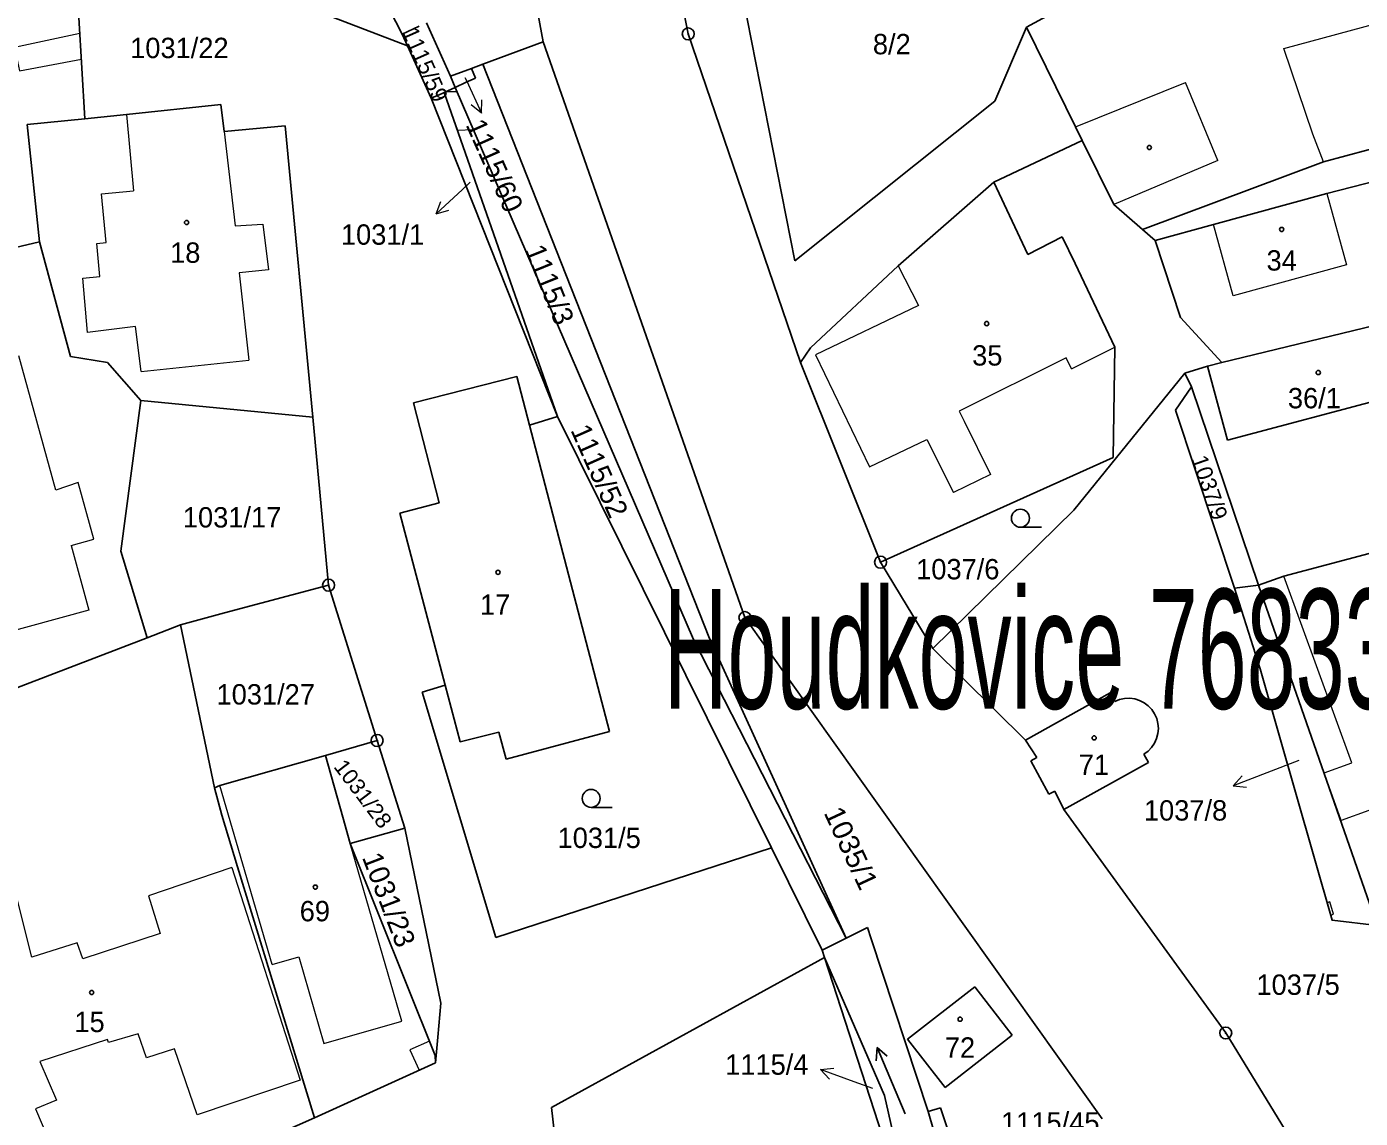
# Model space of a CAD drawing. Extents: x -618848 to -615803, y -1044450 to -1042254.
# Drawn here: x -617086 to -616974.7, y -1043060.3 to -1042969.1 of the extents above; entities that cross this region are included whole.
import ezdxf
from ezdxf.enums import TextEntityAlignment as Align

# ---------------------------------------------------------------- set-up
doc = ezdxf.new("R2010")
doc.units = 0
doc.header["$LTSCALE"] = 0.68
for name, color, linetype, lineweight in [('1', 7, 'Continuous', 25), ('13', 7, 'Continuous', 13), ('3', 7, 'Continuous', 25), ('4', 7, 'Continuous', 13), ('5', 7, 'Continuous', 25), ('7', 7, 'Continuous', 13), ('8', 7, 'Continuous', 25)]:
    doc.layers.add(name, color=color, linetype=linetype, lineweight=lineweight)
doc.layers.add('2', color=7, linetype='Continuous')

msp = doc.modelspace()

# ---------------------------------------------------------------- linework, layer by layer
at = {"layer": '1'}
for p, q in [((-617043.53, -1042906.35), (-617030.78, -1042969.76)), ((-617047.51, -1042945.2), (-617042.89, -1042970.41)), ((-617058.05, -1042963.13), (-617054.66, -1042969.77)), ((-617026.28, -1042966.26), (-617021.89, -1042988.71)), ((-617064.32, -1042966.86), (-617054.22, -1042970.74)), ((-617002.54, -1042969.19), (-616998.53, -1042967.03)), ((-617081.64, -1042968.39), (-617081.14, -1042976.85)), ((-617053.24, -1042969.11), (-617054.66, -1042969.77)), ((-617052.62, -1042968.82), (-617050.63, -1042973.29)), ((-617002.54, -1042969.19), (-617005.19, -1042975.38)), ((-617002.54, -1042969.19), (-616998.44, -1042977.52)), ((-617054.22, -1042970.74), (-617054.66, -1042969.77)), ((-617052.23, -1042975.13), (-617054.22, -1042970.74)), ((-617047.92, -1042972.28), (-617042.89, -1042970.41)), ((-617042.89, -1042970.41), (-617026.04, -1043018.49)), ((-617021.4, -1042997.18), (-617030.78, -1042969.76)), ((-616977.74, -1042980.44), (-616945.54, -1042971.66)), ((-617050.63, -1042973.29), (-617048.88, -1042972.64)), ((-617048.88, -1042972.64), (-617047.92, -1042972.28)), ((-617048.88, -1042972.64), (-617048.54, -1042973.44)), ((-617047.92, -1042972.28), (-617029.07, -1043020.1)), ((-617050.63, -1042973.29), (-617050.23, -1042974.22)), ((-617048.54, -1042973.44), (-617049.31, -1042973.79)), ((-617052.23, -1042975.13), (-617051.31, -1042974.72)), ((-617052.23, -1042975.13), (-617041.69, -1043001.71)), ((-617051.31, -1042974.72), (-617051.15, -1042974.65)), ((-617051.15, -1042974.65), (-617041.69, -1043001.71)), ((-617050.23, -1042974.22), (-617030.33, -1043020.31)), ((-617077.67, -1042976.48), (-617069.79, -1042975.66)), ((-617069.79, -1042975.66), (-617069.53, -1042977.91)), ((-617005.19, -1042975.38), (-617021.89, -1042988.71)), ((-617085.97, -1042977.32), (-617081.14, -1042976.85)), ((-617085.97, -1042977.32), (-617084.93, -1042987.12)), ((-617081.14, -1042976.85), (-617077.67, -1042976.48)), ((-617069.53, -1042977.91), (-617064.42, -1042977.43)), ((-617062.13, -1043001.76), (-617064.42, -1042977.43)), ((-616998.44, -1042977.52), (-616997.89, -1042978.64)), ((-617005.26, -1042982.12), (-616997.89, -1042978.64)), ((-616997.89, -1042978.64), (-616995.25, -1042984.01)), ((-616992.84, -1042986.09), (-616977.74, -1042980.44)), ((-616977.45, -1042983.07), (-616966.6, -1042980.27)), ((-617005.26, -1042982.12), (-617013.24, -1042989.13)), ((-617002.42, -1042988.18), (-617005.26, -1042982.12)), ((-616986.92, -1042985.66), (-616977.45, -1042983.07)), ((-616995.25, -1042984.01), (-616992.84, -1042986.09)), ((-616992.84, -1042986.09), (-616991.78, -1042987.01)), ((-616991.78, -1042987.01), (-616986.92, -1042985.66)), ((-617084.93, -1042987.12), (-617098.16, -1042990.2)), ((-617084.93, -1042987.12), (-617082.34, -1042996.69)), ((-616999.56, -1042986.7), (-617002.42, -1042988.18)), ((-616998.48, -1042988.92), (-616999.56, -1042986.7)), ((-616991.78, -1042987.01), (-616989.68, -1042993.44)), ((-617013.24, -1042989.13), (-617020.57, -1042995.97)), ((-616995.15, -1042995.92), (-616998.48, -1042988.92)), ((-616989.68, -1042993.44), (-616986.24, -1042997.18)), ((-617020.57, -1042995.97), (-617021.4, -1042997.18)), ((-616995.29, -1043005.13), (-616995.15, -1042995.92)), ((-617082.34, -1042996.69), (-617079.25, -1042997.2)), ((-617079.25, -1042997.2), (-617076.49, -1043000.36)), ((-617014.72, -1043013.86), (-617021.4, -1042997.18)), ((-616989.33, -1042998.09), (-616987.42, -1042997.5)), ((-616986.24, -1042997.18), (-616987.42, -1042997.5)), ((-616987.42, -1042997.5), (-616985.76, -1043003.68)), ((-617053.71, -1043000.57), (-617045.09, -1042998.36)), ((-617045.09, -1042998.36), (-617044.03, -1043002.41)), ((-616998.58, -1043009.51), (-616989.33, -1042998.09)), ((-616989.33, -1042998.09), (-616988.76, -1042999.23)), ((-616985.76, -1043003.68), (-616966.15, -1042998.47)), ((-616990.1, -1043001.17), (-616988.76, -1042999.23)), ((-616988.76, -1042999.23), (-616983.16, -1043015.79)), ((-617076.49, -1043000.36), (-617078.16, -1043012.93)), ((-617062.13, -1043001.76), (-617076.49, -1043000.36)), ((-617051.57, -1043008.91), (-617053.71, -1043000.57)), ((-617062.13, -1043001.76), (-617061.54, -1043008.01)), ((-617044.03, -1043002.41), (-617041.69, -1043001.71)), ((-617041.69, -1043001.71), (-617023.83, -1043037.72)), ((-616985.17, -1043016.04), (-616990.1, -1043001.17)), ((-617044.03, -1043002.41), (-617037.34, -1043028)), ((-617014.72, -1043013.86), (-616995.29, -1043005.13)), ((-617061.54, -1043008.01), (-617061.2, -1043011.6)), ((-617054.85, -1043009.77), (-617051.57, -1043008.91)), ((-617051.07, -1043024.13), (-617054.85, -1043009.77)), ((-617010.36, -1043021.08), (-616998.58, -1043009.51)), ((-616960.94, -1043009.72), (-616981.06, -1043015.02)), ((-617061.2, -1043011.6), (-617060.8, -1043015.78)), ((-617075.96, -1043020.18), (-617078.16, -1043012.93)), ((-617010.36, -1043021.08), (-617014.72, -1043013.86)), ((-616981.06, -1043015.02), (-616983.16, -1043015.79)), ((-617060.8, -1043015.78), (-617069.49, -1043018.1)), ((-617056.75, -1043028.75), (-617060.8, -1043015.78)), ((-616983.16, -1043015.79), (-616985.17, -1043016.04)), ((-616985.17, -1043016.04), (-616983.03, -1043022.76)), ((-616983.16, -1043015.79), (-616973.26, -1043044.2)), ((-617069.49, -1043018.1), (-617073.16, -1043019.08)), ((-616996.21, -1043060.33), (-617026.04, -1043018.49)), ((-617075.96, -1043020.18), (-617073.16, -1043019.08)), ((-617070.34, -1043032.7), (-617073.16, -1043019.08)), ((-617093.17, -1043026.77), (-617075.96, -1043020.18)), ((-617017.59, -1043045.24), (-617030.33, -1043020.31)), ((-617017.59, -1043045.24), (-617029.07, -1043020.1)), ((-617010.36, -1043021.08), (-617002.61, -1043028.71)), ((-617051.07, -1043024.13), (-617052.98, -1043024.7)), ((-617049.82, -1043028.87), (-617051.07, -1043024.13)), ((-617046.85, -1043045.2), (-617052.98, -1043024.7)), ((-617002.61, -1043028.71), (-616995.55, -1043024.78)), ((-616995.16, -1043025.48), (-616995.55, -1043024.78)), ((-617046.58, -1043028.04), (-617049.82, -1043028.87)), ((-617045.98, -1043030.3), (-617046.58, -1043028.04)), ((-617045.98, -1043030.3), (-617037.34, -1043028)), ((-617001.66, -1043030.16), (-617002.61, -1043028.71)), ((-617061.07, -1043030), (-617056.75, -1043028.75)), ((-617056.75, -1043028.75), (-617054.45, -1043036.07)), ((-617061.07, -1043030), (-617069.89, -1043032.52)), ((-617059.61, -1043035.14), (-617061.07, -1043030)), ((-617002.18, -1043030.44), (-617001.66, -1043030.16)), ((-617000.68, -1043033.22), (-617002.18, -1043030.44)), ((-616992.34, -1043030.58), (-616999.43, -1043034.5)), ((-616992.73, -1043029.88), (-616992.34, -1043030.58)), ((-617069.89, -1043032.52), (-617070.34, -1043032.7)), ((-617070.34, -1043032.7), (-617069.72, -1043034.98)), ((-617000.18, -1043032.97), (-617000.68, -1043033.22)), ((-616999.43, -1043034.5), (-617000.18, -1043032.97)), ((-617069.72, -1043034.98), (-617068.41, -1043039.3)), ((-617059.61, -1043035.14), (-617058.99, -1043037.36)), ((-616985.9, -1043053.17), (-616999.43, -1043034.5)), ((-617054.45, -1043036.07), (-617058.99, -1043037.36)), ((-617051.43, -1043050.68), (-617054.45, -1043036.07)), ((-617058.99, -1043037.36), (-617051.9, -1043055.06)), ((-617046.85, -1043045.2), (-617023.83, -1043037.72)), ((-617023.83, -1043037.72), (-617019.6, -1043046.25)), ((-617061.97, -1043060.26), (-617068.41, -1043039.3)), ((-617017.59, -1043045.24), (-617019.6, -1043046.25)), ((-617015.81, -1043044.35), (-617017.59, -1043045.24)), ((-617015.5, -1043045.3), (-617015.81, -1043044.35)), ((-617010.75, -1043059.73), (-617015.5, -1043045.3)), ((-617019.6, -1043046.25), (-617019.4, -1043046.86)), ((-617042.18, -1043059.39), (-617019.4, -1043046.86)), ((-617019.4, -1043046.86), (-617014.4, -1043058.4)), ((-617010.51, -1043074.19), (-617019.4, -1043046.86)), ((-617012.46, -1043053.68), (-617006.85, -1043049.33)), ((-617003.72, -1043053.36), (-617006.85, -1043049.33)), ((-617051.68, -1043053.52), (-617051.43, -1043050.68)), ((-616956.7, -1043100.86), (-616985.9, -1043053.17)), ((-617051.87, -1043055.66), (-617051.68, -1043053.52)), ((-617009.33, -1043057.71), (-617012.46, -1043053.68)), ((-617009.33, -1043057.71), (-617003.72, -1043053.36)), ((-617051.9, -1043055.06), (-617051.87, -1043055.66)), ((-617051.87, -1043055.66), (-617061.97, -1043060.26)), ((-617012.29, -1043067.61), (-617014.4, -1043058.4)), ((-617041.33, -1043067.24), (-617042.18, -1043059.39)), ((-617009.72, -1043059.42), (-617010.75, -1043059.73)), ((-617010.75, -1043059.73), (-617009.38, -1043064.36)), ((-617008.17, -1043063.97), (-617009.72, -1043059.42)), ((-617082.94, -1043069.46), (-617061.97, -1043060.26))]:
    msp.add_line(p, q, dxfattribs=at)
for points in [[(-617051.15, -1042974.65), (-617050.23, -1042974.22), (-617049.31, -1042973.79)], [(-616957.61, -1042990.27), (-616963.39, -1042991.64), (-616986.24, -1042997.18)], [(-616983.03, -1043022.76), (-616977.02, -1043043.76), (-616973.26, -1043044.2)], [(-616995.16, -1043025.48), (-616994.763, -1043025.323), (-616994.346, -1043025.235), (-616993.919, -1043025.219), (-616993.497, -1043025.275), (-616993.089, -1043025.402), (-616992.709, -1043025.596), (-616992.367, -1043025.851), (-616992.074, -1043026.161), (-616991.836, -1043026.515), (-616991.663, -1043026.905), (-616991.557, -1043027.319), (-616991.523, -1043027.744), (-616991.561, -1043028.169), (-616991.671, -1043028.581), (-616991.848, -1043028.969), (-616992.089, -1043029.321), (-616992.386, -1043029.628), (-616992.73, -1043029.88)]]:
    msp.add_lwpolyline(points, dxfattribs=at)
at = {"layer": '13'}
for points in [[(-617086.62, -1042972.85), (-617081.44, -1042971.85), (-617081.56, -1042969.73), (-617087.02, -1042970.89)], [(-617050.05, -1042977.79), (-617048.72, -1042977.73), (-617050.08, -1042974.58), (-617051.03, -1042974.59), (-617051.15, -1042974.65)], [(-616977.44, -1043042.3), (-616977.14, -1043043.33), (-616976.9, -1043043.26), (-616977.2, -1043042.23)], [(-617054.01, -1043054.58), (-617053.24, -1043056.28), (-617051.87, -1043055.66), (-617051.9, -1043055.06), (-617052.39, -1043053.84)]]:
    msp.add_lwpolyline(points, close=True, dxfattribs=at)
at = {"layer": '3'}
for p, q in [((-617003.043, -1043010.94), (-617001.293, -1043010.94)), ((-617038.883, -1043034.33), (-617037.133, -1043034.33)), ((-617015.001, -1043054.389), (-617014.158, -1043055.093))]:
    msp.add_line(p, q, dxfattribs=at)
msp.add_lwpolyline([(-617012.657, -1043059.912), (-617015.001, -1043054.389), (-617015.081, -1043055.485)], dxfattribs=at)
for centre in [(-617003.0429, -1043010.1898), (-617038.8829, -1043033.5798)]:
    msp.add_circle(centre, 0.75, dxfattribs=at)
at = {"layer": '4'}
for p, q in [((-616981.04, -1042970.98), (-616949.5, -1042962.44)), ((-616978.62, -1042978.13), (-616981.04, -1042970.98)), ((-616998.44, -1042977.52), (-616989.25, -1042973.81)), ((-616986.55, -1042980.33), (-616989.25, -1042973.81)), ((-617077.67, -1042976.48), (-617077.09, -1042982.86)), ((-617069.53, -1042977.91), (-617068.61, -1042985.78)), ((-616977.74, -1042980.44), (-616978.62, -1042978.13)), ((-616986.55, -1042980.33), (-616995.25, -1042984.01)), ((-617079.75, -1042983.11), (-617077.09, -1042982.86)), ((-616977.45, -1042983.07), (-616975.81, -1042989.03)), ((-617079.37, -1042987.18), (-617079.75, -1042983.11)), ((-617068.61, -1042985.78), (-617066.28, -1042985.63)), ((-617066.28, -1042985.63), (-617065.82, -1042989.44)), ((-616985.27, -1042991.62), (-616986.92, -1042985.66)), ((-617080.16, -1042987.25), (-617079.37, -1042987.18)), ((-617079.9, -1042990.01), (-617080.16, -1042987.25)), ((-617065.82, -1042989.44), (-617068.26, -1042989.7)), ((-617068.26, -1042989.7), (-617067.46, -1042996.99)), ((-617013.24, -1042989.13), (-617011.56, -1042992.44)), ((-616975.81, -1042989.03), (-616985.27, -1042991.62)), ((-617081.31, -1042990.14), (-617079.9, -1042990.01)), ((-617080.93, -1042994.68), (-617081.31, -1042990.14)), ((-617011.56, -1042992.44), (-617020.15, -1042996.55)), ((-617076.91, -1042994.19), (-617080.93, -1042994.68)), ((-617076.45, -1042997.95), (-617076.91, -1042994.19)), ((-616998.77, -1042997.72), (-616995.15, -1042995.92)), ((-617083.57, -1043007.84), (-617086.66, -1042996.62)), ((-617076.45, -1042997.95), (-617067.46, -1042996.99)), ((-617020.15, -1042996.55), (-617015.63, -1043005.89)), ((-616999.21, -1042996.81), (-617008.15, -1043001.24)), ((-616998.77, -1042997.72), (-616999.21, -1042996.81)), ((-617008.15, -1043001.24), (-617007.73, -1043002.1)), ((-617007.73, -1043002.1), (-617005.55, -1043006.55)), ((-617015.63, -1043005.89), (-617010.86, -1043003.63)), ((-617010.86, -1043003.63), (-617008.62, -1043008.04)), ((-617081.7, -1043007.2), (-617083.57, -1043007.84)), ((-617080.41, -1043011.94), (-617081.7, -1043007.2)), ((-617005.55, -1043006.55), (-617008.62, -1043008.04)), ((-617082.3, -1043012.47), (-617080.41, -1043011.94)), ((-617082.3, -1043012.47), (-617080.82, -1043017.86)), ((-616975.38, -1043030.6), (-616981.06, -1043015.02)), ((-617080.82, -1043017.86), (-617093.27, -1043021.28)), ((-616977.68, -1043031.45), (-616975.38, -1043030.6)), ((-616976.26, -1043035.43), (-616977.68, -1043031.45)), ((-617065.51, -1043047.44), (-617069.89, -1043032.52)), ((-616973.95, -1043034.6), (-616976.26, -1043035.43)), ((-617054.7, -1043052.17), (-617058.99, -1043037.36)), ((-617068.88, -1043039.34), (-617063.17, -1043057.1)), ((-617065.51, -1043047.44), (-617063.29, -1043046.82)), ((-617063.29, -1043046.82), (-617061.2, -1043054.05)), ((-617061.2, -1043054.05), (-617054.7, -1043052.17)), ((-617079.25, -1043053.72), (-617084.91, -1043055.54)), ((-617079.18, -1043053.97), (-617079.25, -1043053.72)), ((-617076.69, -1043053.24), (-617079.18, -1043053.97)), ((-617076, -1043055.25), (-617076.69, -1043053.24)), ((-617073.66, -1043054.49), (-617076, -1043055.25)), ((-617071.77, -1043059.99), (-617073.66, -1043054.49)), ((-617084.91, -1043055.54), (-617083.53, -1043058.78)), ((-617063.17, -1043057.1), (-617071.77, -1043059.99))]:
    msp.add_line(p, q, dxfattribs=at)
for points in [[(-617068.88, -1043039.34), (-617075.83, -1043041.71), (-617074.85, -1043044.86), (-617081.33, -1043046.98), (-617081.8, -1043045.64), (-617085.58, -1043046.85), (-617088.09, -1043036.87)], [(-617083.53, -1043058.78), (-617085.27, -1043059.49), (-617081.87, -1043067.5)]]:
    msp.add_lwpolyline(points, dxfattribs=at)
at = {"layer": '5'}
for centre in [(-616992.2768, -1042979.2392), (-617072.6568, -1042985.4992), (-616981.2368, -1042986.0792), (-617005.8568, -1042993.9392), (-616978.1768, -1042998.0292), (-617046.6568, -1043014.7092), (-616996.8868, -1043028.5292), (-617061.9068, -1043040.9892), (-617080.5868, -1043049.7892), (-617008.0768, -1043052.0192)]:
    msp.add_circle(centre, 0.175, dxfattribs=at)
at = {"layer": '7'}
for p, q in [((-617048.032, -1042976.37), (-617048.001, -1042975.251)), ((-617051.825, -1042984.787), (-617050.751, -1042984.47)), ((-616985.282, -1043032.535), (-616984.167, -1043032.644)), ((-617019.74, -1043056.224), (-617018.97, -1043057.037))]:
    msp.add_line(p, q, dxfattribs=at)
for points in [[(-617049.42, -1042973.39), (-617049.3, -1042973.65), (-617048.032, -1042976.37), (-617048.909, -1042975.674)], [(-617048.97, -1042982.13), (-617049.63, -1042982.74), (-617051.825, -1042984.787), (-617051.434, -1042983.737)], [(-616979.79, -1043030.43), (-616982.48, -1043031.46), (-616985.282, -1043032.535), (-616984.526, -1043031.709)], [(-617015.37, -1043057.81), (-617016.92, -1043057.25), (-617019.74, -1043056.224), (-617018.628, -1043056.096)]]:
    msp.add_lwpolyline(points, dxfattribs=at)
at = {"layer": '8'}
for centre, radius in [((-617030.78, -1042969.7599), 0.5), ((-617030.78, -1042969.7599), 0.0303), ((-617014.72, -1043013.8599), 0.5), ((-617014.72, -1043013.8599), 0.0303), ((-617060.8, -1043015.7799), 0.5), ((-617060.8, -1043015.7799), 0.0303), ((-617026.04, -1043018.4899), 0.5), ((-617026.04, -1043018.4899), 0.0303), ((-617056.75, -1043028.7499), 0.5), ((-617056.75, -1043028.7499), 0.0303), ((-616985.9, -1043053.1699), 0.5), ((-616985.9, -1043053.1699), 0.0303)]:
    msp.add_circle(centre, radius, dxfattribs=at)

# ---------------------------------------------------------------- texts
at = {"layer": '2'}
for s, height, rotation, p in [('1115/59', 1.362, 294, (-617053.3582, -1042972.5795)), ('1115/3', 1.7, 292, (-617043.128, -1042990.9911)), ('1115/52', 1.7, 294, (-617038.9595, -1043006.5783)), ('1037/9', 1.36, 289, (-616987.8922, -1043007.8431)), ('1031/23', 1.7, 291, (-617056.5563, -1043042.3369))]:
    msp.add_text(s, height=height, rotation=rotation, dxfattribs=at).set_placement(p, align=Align.CENTER)
for s, p in [('8/2', (-617013.78, -1042971.455)), ('1031/22', (-617073.259, -1042971.775)), ('18', (-617072.769, -1042988.865)), ('34', (-616981.229, -1042989.515)), ('35', (-617005.809, -1042997.445)), ('36/1', (-616978.499, -1043001.015)), ('1031/17', (-617068.859, -1043010.965)), ('1037/6', (-617008.27, -1043015.295)), ('17', (-617046.899, -1043018.255)), ('1031/27', (-617066.049, -1043025.745)), ('71', (-616996.909, -1043031.625)), ('1031/5', (-617038.21, -1043037.725)), ('69', (-617061.949, -1043043.845)), ('1037/5', (-616979.86, -1043049.985)), ('15', (-617080.759, -1043053.095)), ('72', (-617008.089, -1043055.235))]:
    msp.add_text(s, height=1.7, dxfattribs=at).set_placement(p, align=Align.CENTER)
msp.add_text('1115/60', height=1.7, rotation=294, dxfattribs=at).set_placement((-617049.383, -1042977.333))
for s, p in [('1031/1', (-617052.819, -1042987.355)), ('1037/8', (-616985.779, -1043035.435)), ('1115/4', (-617020.739, -1043056.655))]:
    msp.add_text(s, height=1.7, dxfattribs=at).set_placement(p, align=Align.RIGHT)
at = {"layer": '2', "width": 1.05}
for s, height, rotation, p in [('1031/28', 1.3, 307, (-617058.4484, -1043033.5843)), ('1035/1', 1.7, 295, (-617017.9499, -1043038.0813))]:
    msp.add_text(s, height=height, rotation=rotation, dxfattribs=at).set_placement(p, align=Align.CENTER)
at = {"layer": '2'}
msp.add_text('1115/45', height=1.7, dxfattribs=at).set_placement((-617004.66, -1043061.485))
at = {"layer": '7', "width": 0.55}
msp.add_text('Houdkovice 768332', height=10, dxfattribs=at).set_placement((-617000.3, -1043026.093), align=Align.CENTER)

doc.saveas('drawing.dxf')
